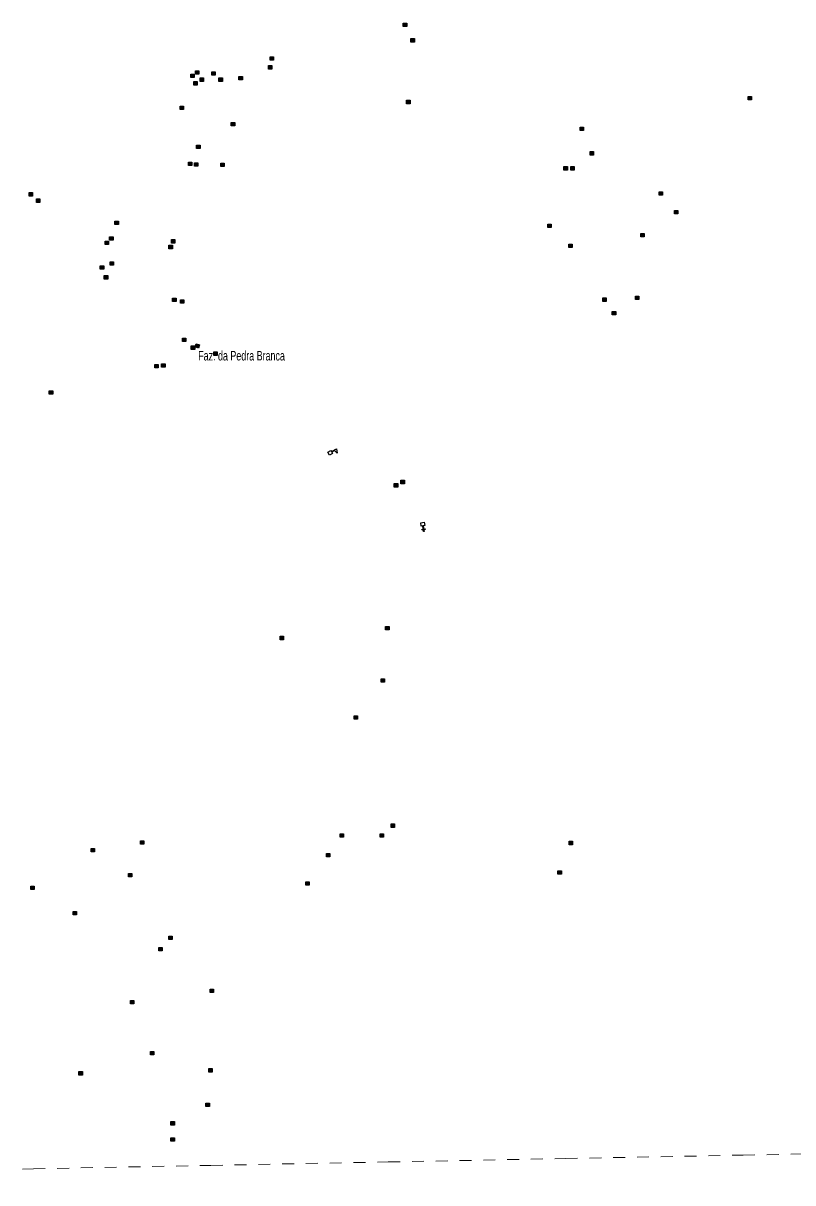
# Model space of a CAD drawing. Extents: x 220.8 to 246.7, y 7287.6 to 7315.8.
# Drawn here: x 227.18 to 233.65, y 7287.6 to 7297.35 of the extents above; entities that cross this region are included whole.
import ezdxf

# ---------------------------------------------------------------- set-up
doc = ezdxf.new("R2010")
doc.units = 0
doc.header["$LTSCALE"] = 0.032
doc.linetypes.add('SHORT_DASHED', pattern=[2.7, 1.5, -1.2])
for name, color, linetype, lineweight in [('2', 7, 'Continuous', 25), ('4', 7, 'Continuous', 25), ('58', 7, 'SHORT_DASHED', 13), ('6', 7, 'Continuous', 25)]:
    doc.layers.add(name, color=color, linetype=linetype, lineweight=lineweight)
doc.layers.add('61', color=7, linetype='Continuous')

msp = doc.modelspace()

# ---------------------------------------------------------------- hatches: boundary and pattern name
at = {"layer": '2'}
for points in [[(230.3759, 7297.3457), (230.4049, 7297.3457), (230.4049, 7297.3167), (230.3759, 7297.3167)], [(230.4409, 7297.2157), (230.4699, 7297.2157), (230.4699, 7297.1867), (230.4409, 7297.1867)], [(229.2429, 7296.9889), (229.2719, 7296.9889), (229.2719, 7296.9599), (229.2429, 7296.9599)], [(229.2571, 7297.063), (229.2861, 7297.063), (229.2861, 7297.034), (229.2571, 7297.034)], [(228.5899, 7296.9176), (228.6189, 7296.9176), (228.6189, 7296.8886), (228.5899, 7296.8886)], [(228.6298, 7296.9461), (228.6588, 7296.9461), (228.6588, 7296.9171), (228.6298, 7296.9171)], [(228.6697, 7296.8862), (228.6987, 7296.8862), (228.6987, 7296.8572), (228.6697, 7296.8572)], [(228.7667, 7296.9376), (228.7957, 7296.9376), (228.7957, 7296.9086), (228.7667, 7296.9086)], [(228.8266, 7296.8862), (228.8556, 7296.8862), (228.8556, 7296.8572), (228.8266, 7296.8572)], [(228.9948, 7296.8976), (229.0238, 7296.8976), (229.0238, 7296.8686), (228.9948, 7296.8686)], [(228.6156, 7296.8549), (228.6446, 7296.8549), (228.6446, 7296.8259), (228.6156, 7296.8259)], [(230.4039, 7296.6982), (230.4329, 7296.6982), (230.4329, 7296.6692), (230.4039, 7296.6692)], [(233.2744, 7296.7298), (233.3034, 7296.7298), (233.3034, 7296.7008), (233.2744, 7296.7008)], [(228.5015, 7296.6496), (228.5305, 7296.6496), (228.5305, 7296.6206), (228.5015, 7296.6206)], [(228.9304, 7296.5114), (228.9594, 7296.5114), (228.9594, 7296.4824), (228.9304, 7296.4824)], [(231.8628, 7296.4719), (231.8918, 7296.4719), (231.8918, 7296.4429), (231.8628, 7296.4429)], [(228.6396, 7296.322), (228.6686, 7296.322), (228.6686, 7296.293), (228.6396, 7296.293)], [(231.9459, 7296.2671), (231.9749, 7296.2671), (231.9749, 7296.2381), (231.9459, 7296.2381)], [(228.5702, 7296.178), (228.5992, 7296.178), (228.5992, 7296.149), (228.5702, 7296.149)], [(228.6209, 7296.1727), (228.6499, 7296.1727), (228.6499, 7296.1437), (228.6209, 7296.1437)], [(228.8424, 7296.17), (228.8714, 7296.17), (228.8714, 7296.141), (228.8424, 7296.141)], [(231.726, 7296.1413), (231.755, 7296.1413), (231.755, 7296.1123), (231.726, 7296.1123)], [(231.7833, 7296.1413), (231.8123, 7296.1413), (231.8123, 7296.1123), (231.7833, 7296.1123)], [(227.2319, 7295.9222), (227.2609, 7295.9222), (227.2609, 7295.8932), (227.2319, 7295.8932)], [(232.5251, 7295.9299), (232.5541, 7295.9299), (232.5541, 7295.9009), (232.5251, 7295.9009)], [(227.2935, 7295.8694), (227.3225, 7295.8694), (227.3225, 7295.8404), (227.2935, 7295.8404)], [(232.6541, 7295.7722), (232.6831, 7295.7722), (232.6831, 7295.7432), (232.6541, 7295.7432)], [(227.9532, 7295.6826), (227.9822, 7295.6826), (227.9822, 7295.6536), (227.9532, 7295.6536)], [(231.5898, 7295.6575), (231.6188, 7295.6575), (231.6188, 7295.6285), (231.5898, 7295.6285)], [(227.9085, 7295.5519), (227.9375, 7295.5519), (227.9375, 7295.5229), (227.9085, 7295.5229)], [(228.4278, 7295.5278), (228.4568, 7295.5278), (228.4568, 7295.4988), (228.4278, 7295.4988)], [(232.371, 7295.5787), (232.4, 7295.5787), (232.4, 7295.5497), (232.371, 7295.5497)], [(227.8707, 7295.5141), (227.8997, 7295.5141), (227.8997, 7295.4851), (227.8707, 7295.4851)], [(228.4071, 7295.4797), (228.4361, 7295.4797), (228.4361, 7295.4507), (228.4071, 7295.4507)], [(231.7662, 7295.4896), (231.7952, 7295.4896), (231.7952, 7295.4606), (231.7662, 7295.4606)], [(227.9119, 7295.3421), (227.9409, 7295.3421), (227.9409, 7295.3131), (227.9119, 7295.3131)], [(227.8294, 7295.3078), (227.8584, 7295.3078), (227.8584, 7295.2788), (227.8294, 7295.2788)], [(227.8638, 7295.2252), (227.8928, 7295.2252), (227.8928, 7295.1962), (227.8638, 7295.1962)], [(228.4381, 7295.0361), (228.4671, 7295.0361), (228.4671, 7295.0071), (228.4381, 7295.0071)], [(232.0521, 7295.0379), (232.0811, 7295.0379), (232.0811, 7295.0089), (232.0521, 7295.0089)], [(232.3265, 7295.0522), (232.3555, 7295.0522), (232.3555, 7295.0232), (232.3265, 7295.0232)], [(228.5034, 7295.0223), (228.5324, 7295.0223), (228.5324, 7294.9933), (228.5034, 7294.9933)], [(232.1321, 7294.9235), (232.1611, 7294.9235), (232.1611, 7294.8945), (232.1321, 7294.8945)], [(228.5198, 7294.6999), (228.5488, 7294.6999), (228.5488, 7294.6709), (228.5198, 7294.6709)], [(228.6359, 7294.6532), (228.6634, 7294.644), (228.6542, 7294.6165), (228.6267, 7294.6256)], [(228.595, 7294.6344), (228.624, 7294.6344), (228.624, 7294.6054), (228.595, 7294.6054)], [(228.7842, 7294.5835), (228.8132, 7294.5835), (228.8132, 7294.5545), (228.7842, 7294.5545)], [(228.287, 7294.4792), (228.316, 7294.4792), (228.316, 7294.4502), (228.287, 7294.4502)], [(228.3452, 7294.4841), (228.3742, 7294.4841), (228.3742, 7294.4551), (228.3452, 7294.4551)], [(227.4017, 7294.257), (227.4307, 7294.257), (227.4307, 7294.228), (227.4017, 7294.228)], [(230.3001, 7293.4774), (230.3291, 7293.4774), (230.3291, 7293.4484), (230.3001, 7293.4484)], [(230.3569, 7293.5058), (230.3859, 7293.5058), (230.3859, 7293.4768), (230.3569, 7293.4768)], [(230.2279, 7292.2771), (230.2569, 7292.2771), (230.2569, 7292.2481), (230.2279, 7292.2481)], [(229.3417, 7292.1953), (229.3707, 7292.1953), (229.3707, 7292.1663), (229.3417, 7292.1663)], [(230.1903, 7291.8385), (230.2193, 7291.8385), (230.2193, 7291.8095), (230.1903, 7291.8095)], [(229.9636, 7291.5279), (229.9926, 7291.5279), (229.9926, 7291.4989), (229.9636, 7291.4989)], [(230.2736, 7290.6188), (230.3026, 7290.6188), (230.3026, 7290.5898), (230.2736, 7290.5898)], [(228.1679, 7290.4762), (228.1969, 7290.4762), (228.1969, 7290.4472), (228.1679, 7290.4472)], [(229.8454, 7290.535), (229.8744, 7290.535), (229.8744, 7290.506), (229.8454, 7290.506)], [(230.1805, 7290.535), (230.2095, 7290.535), (230.2095, 7290.506), (230.1805, 7290.506)], [(231.7699, 7290.4726), (231.7989, 7290.4726), (231.7989, 7290.4436), (231.7699, 7290.4436)], [(227.7523, 7290.4124), (227.7813, 7290.4124), (227.7813, 7290.3834), (227.7523, 7290.3834)], [(229.7306, 7290.3706), (229.7596, 7290.3706), (229.7596, 7290.3416), (229.7306, 7290.3416)], [(228.0674, 7290.2026), (228.0964, 7290.2026), (228.0964, 7290.1736), (228.0674, 7290.1736)], [(231.6762, 7290.2249), (231.7052, 7290.2249), (231.7052, 7290.1959), (231.6762, 7290.1959)], [(227.2465, 7290.0961), (227.2755, 7290.0961), (227.2755, 7290.0671), (227.2465, 7290.0671)], [(229.5573, 7290.1332), (229.5863, 7290.1332), (229.5863, 7290.1042), (229.5573, 7290.1042)], [(227.6008, 7289.8829), (227.6298, 7289.8829), (227.6298, 7289.8539), (227.6008, 7289.8539)], [(228.3219, 7289.5803), (228.3509, 7289.5803), (228.3509, 7289.5513), (228.3219, 7289.5513)], [(228.4056, 7289.6759), (228.4346, 7289.6759), (228.4346, 7289.6469), (228.4056, 7289.6469)], [(228.7524, 7289.2306), (228.7814, 7289.2306), (228.7814, 7289.2016), (228.7524, 7289.2016)], [(228.0827, 7289.1361), (228.1117, 7289.1361), (228.1117, 7289.1071), (228.0827, 7289.1071)], [(228.2515, 7288.7066), (228.2805, 7288.7066), (228.2805, 7288.6776), (228.2515, 7288.6776)], [(227.6511, 7288.5381), (227.6801, 7288.5381), (227.6801, 7288.5091), (227.6511, 7288.5091)], [(228.7419, 7288.5626), (228.7709, 7288.5626), (228.7709, 7288.5336), (228.7419, 7288.5336)], [(228.718, 7288.2723), (228.747, 7288.2723), (228.747, 7288.2433), (228.718, 7288.2433)], [(228.4237, 7288.1172), (228.4527, 7288.1172), (228.4527, 7288.0882), (228.4237, 7288.0882)], [(228.4237, 7287.982), (228.4527, 7287.982), (228.4527, 7287.953), (228.4237, 7287.953)]]:
    msp.add_hatch(color=256, dxfattribs=at).paths.add_polyline_path(points)

# ---------------------------------------------------------------- linework, layer by layer
for points in [[(230.3759, 7297.3457), (230.4049, 7297.3457), (230.4049, 7297.3167), (230.3759, 7297.3167)], [(230.4409, 7297.2157), (230.4699, 7297.2157), (230.4699, 7297.1867), (230.4409, 7297.1867)], [(229.2429, 7296.9889), (229.2719, 7296.9889), (229.2719, 7296.9599), (229.2429, 7296.9599)], [(229.2571, 7297.063), (229.2861, 7297.063), (229.2861, 7297.034), (229.2571, 7297.034)], [(228.5899, 7296.9176), (228.6189, 7296.9176), (228.6189, 7296.8886), (228.5899, 7296.8886)], [(228.6298, 7296.9461), (228.6588, 7296.9461), (228.6588, 7296.9171), (228.6298, 7296.9171)], [(228.6697, 7296.8862), (228.6987, 7296.8862), (228.6987, 7296.8572), (228.6697, 7296.8572)], [(228.7667, 7296.9376), (228.7957, 7296.9376), (228.7957, 7296.9086), (228.7667, 7296.9086)], [(228.8266, 7296.8862), (228.8556, 7296.8862), (228.8556, 7296.8572), (228.8266, 7296.8572)], [(228.9948, 7296.8976), (229.0238, 7296.8976), (229.0238, 7296.8686), (228.9948, 7296.8686)], [(228.6156, 7296.8549), (228.6446, 7296.8549), (228.6446, 7296.8259), (228.6156, 7296.8259)], [(230.4039, 7296.6982), (230.4329, 7296.6982), (230.4329, 7296.6692), (230.4039, 7296.6692)], [(233.2744, 7296.7298), (233.3034, 7296.7298), (233.3034, 7296.7008), (233.2744, 7296.7008)], [(228.5015, 7296.6496), (228.5305, 7296.6496), (228.5305, 7296.6206), (228.5015, 7296.6206)], [(228.9304, 7296.5114), (228.9594, 7296.5114), (228.9594, 7296.4824), (228.9304, 7296.4824)], [(231.8628, 7296.4719), (231.8918, 7296.4719), (231.8918, 7296.4429), (231.8628, 7296.4429)], [(228.6396, 7296.322), (228.6686, 7296.322), (228.6686, 7296.293), (228.6396, 7296.293)], [(231.9459, 7296.2671), (231.9749, 7296.2671), (231.9749, 7296.2381), (231.9459, 7296.2381)], [(228.5702, 7296.178), (228.5992, 7296.178), (228.5992, 7296.149), (228.5702, 7296.149)], [(228.6209, 7296.1727), (228.6499, 7296.1727), (228.6499, 7296.1437), (228.6209, 7296.1437)], [(228.8424, 7296.17), (228.8714, 7296.17), (228.8714, 7296.141), (228.8424, 7296.141)], [(231.726, 7296.1413), (231.755, 7296.1413), (231.755, 7296.1123), (231.726, 7296.1123)], [(231.7833, 7296.1413), (231.8123, 7296.1413), (231.8123, 7296.1123), (231.7833, 7296.1123)], [(227.2319, 7295.9222), (227.2609, 7295.9222), (227.2609, 7295.8932), (227.2319, 7295.8932)], [(232.5251, 7295.9299), (232.5541, 7295.9299), (232.5541, 7295.9009), (232.5251, 7295.9009)], [(227.2935, 7295.8694), (227.3225, 7295.8694), (227.3225, 7295.8404), (227.2935, 7295.8404)], [(232.6541, 7295.7722), (232.6831, 7295.7722), (232.6831, 7295.7432), (232.6541, 7295.7432)], [(227.9532, 7295.6826), (227.9822, 7295.6826), (227.9822, 7295.6536), (227.9532, 7295.6536)], [(231.5898, 7295.6575), (231.6188, 7295.6575), (231.6188, 7295.6285), (231.5898, 7295.6285)], [(227.9085, 7295.5519), (227.9375, 7295.5519), (227.9375, 7295.5229), (227.9085, 7295.5229)], [(228.4278, 7295.5278), (228.4568, 7295.5278), (228.4568, 7295.4988), (228.4278, 7295.4988)], [(232.371, 7295.5787), (232.4, 7295.5787), (232.4, 7295.5497), (232.371, 7295.5497)], [(227.8707, 7295.5141), (227.8997, 7295.5141), (227.8997, 7295.4851), (227.8707, 7295.4851)], [(228.4071, 7295.4797), (228.4361, 7295.4797), (228.4361, 7295.4507), (228.4071, 7295.4507)], [(231.7662, 7295.4896), (231.7952, 7295.4896), (231.7952, 7295.4606), (231.7662, 7295.4606)], [(227.9119, 7295.3421), (227.9409, 7295.3421), (227.9409, 7295.3131), (227.9119, 7295.3131)], [(227.8294, 7295.3078), (227.8584, 7295.3078), (227.8584, 7295.2788), (227.8294, 7295.2788)], [(227.8638, 7295.2252), (227.8928, 7295.2252), (227.8928, 7295.1962), (227.8638, 7295.1962)], [(228.4381, 7295.0361), (228.4671, 7295.0361), (228.4671, 7295.0071), (228.4381, 7295.0071)], [(232.0521, 7295.0379), (232.0811, 7295.0379), (232.0811, 7295.0089), (232.0521, 7295.0089)], [(232.3265, 7295.0522), (232.3555, 7295.0522), (232.3555, 7295.0232), (232.3265, 7295.0232)], [(228.5034, 7295.0223), (228.5324, 7295.0223), (228.5324, 7294.9933), (228.5034, 7294.9933)], [(232.1321, 7294.9235), (232.1611, 7294.9235), (232.1611, 7294.8945), (232.1321, 7294.8945)], [(228.5198, 7294.6999), (228.5488, 7294.6999), (228.5488, 7294.6709), (228.5198, 7294.6709)], [(228.6359, 7294.6532), (228.6634, 7294.644), (228.6542, 7294.6165), (228.6267, 7294.6256)], [(228.595, 7294.6344), (228.624, 7294.6344), (228.624, 7294.6054), (228.595, 7294.6054)], [(228.7842, 7294.5835), (228.8132, 7294.5835), (228.8132, 7294.5545), (228.7842, 7294.5545)], [(228.287, 7294.4792), (228.316, 7294.4792), (228.316, 7294.4502), (228.287, 7294.4502)], [(228.3452, 7294.4841), (228.3742, 7294.4841), (228.3742, 7294.4551), (228.3452, 7294.4551)], [(227.4017, 7294.257), (227.4307, 7294.257), (227.4307, 7294.228), (227.4017, 7294.228)], [(230.3001, 7293.4774), (230.3291, 7293.4774), (230.3291, 7293.4484), (230.3001, 7293.4484)], [(230.3569, 7293.5058), (230.3859, 7293.5058), (230.3859, 7293.4768), (230.3569, 7293.4768)], [(230.2279, 7292.2771), (230.2569, 7292.2771), (230.2569, 7292.2481), (230.2279, 7292.2481)], [(229.3417, 7292.1953), (229.3707, 7292.1953), (229.3707, 7292.1663), (229.3417, 7292.1663)], [(230.1903, 7291.8385), (230.2193, 7291.8385), (230.2193, 7291.8095), (230.1903, 7291.8095)], [(229.9636, 7291.5279), (229.9926, 7291.5279), (229.9926, 7291.4989), (229.9636, 7291.4989)], [(230.2736, 7290.6188), (230.3026, 7290.6188), (230.3026, 7290.5898), (230.2736, 7290.5898)], [(228.1679, 7290.4762), (228.1969, 7290.4762), (228.1969, 7290.4472), (228.1679, 7290.4472)], [(229.8454, 7290.535), (229.8744, 7290.535), (229.8744, 7290.506), (229.8454, 7290.506)], [(230.1805, 7290.535), (230.2095, 7290.535), (230.2095, 7290.506), (230.1805, 7290.506)], [(231.7699, 7290.4726), (231.7989, 7290.4726), (231.7989, 7290.4436), (231.7699, 7290.4436)], [(227.7523, 7290.4124), (227.7813, 7290.4124), (227.7813, 7290.3834), (227.7523, 7290.3834)], [(229.7306, 7290.3706), (229.7596, 7290.3706), (229.7596, 7290.3416), (229.7306, 7290.3416)], [(228.0674, 7290.2026), (228.0964, 7290.2026), (228.0964, 7290.1736), (228.0674, 7290.1736)], [(231.6762, 7290.2249), (231.7052, 7290.2249), (231.7052, 7290.1959), (231.6762, 7290.1959)], [(227.2465, 7290.0961), (227.2755, 7290.0961), (227.2755, 7290.0671), (227.2465, 7290.0671)], [(229.5573, 7290.1332), (229.5863, 7290.1332), (229.5863, 7290.1042), (229.5573, 7290.1042)], [(227.6008, 7289.8829), (227.6298, 7289.8829), (227.6298, 7289.8539), (227.6008, 7289.8539)], [(228.3219, 7289.5803), (228.3509, 7289.5803), (228.3509, 7289.5513), (228.3219, 7289.5513)], [(228.4056, 7289.6759), (228.4346, 7289.6759), (228.4346, 7289.6469), (228.4056, 7289.6469)], [(228.7524, 7289.2306), (228.7814, 7289.2306), (228.7814, 7289.2016), (228.7524, 7289.2016)], [(228.0827, 7289.1361), (228.1117, 7289.1361), (228.1117, 7289.1071), (228.0827, 7289.1071)], [(228.2515, 7288.7066), (228.2805, 7288.7066), (228.2805, 7288.6776), (228.2515, 7288.6776)], [(227.6511, 7288.5381), (227.6801, 7288.5381), (227.6801, 7288.5091), (227.6511, 7288.5091)], [(228.7419, 7288.5626), (228.7709, 7288.5626), (228.7709, 7288.5336), (228.7419, 7288.5336)], [(228.718, 7288.2723), (228.747, 7288.2723), (228.747, 7288.2433), (228.718, 7288.2433)], [(228.4237, 7288.1172), (228.4527, 7288.1172), (228.4527, 7288.0882), (228.4237, 7288.0882)], [(228.4237, 7287.982), (228.4527, 7287.982), (228.4527, 7287.953), (228.4237, 7287.953)]]:
    msp.add_lwpolyline(points, close=True, dxfattribs=at)
at = {"layer": '4'}
for points in [[(229.7733, 7293.7462), (229.8157, 7293.7695), (229.8219, 7293.7342), (229.7986, 7293.7545), (229.7757, 7293.7419)], [(229.7757, 7293.7419), (229.7815, 7293.7313), (229.7561, 7293.7173), (229.7421, 7293.7427), (229.7676, 7293.7567), (229.7733, 7293.7462)]]:
    msp.add_lwpolyline(points, dxfattribs=at)
at = {"layer": '58'}
msp.add_lwpolyline([(221.3035, 7287.6034), (222.7945, 7287.633), (224.2855, 7287.6625), (225.7765, 7287.6918), (227.2675, 7287.7209), (228.7585, 7287.7499), (230.2495, 7287.7787), (231.7405, 7287.8074), (233.2315, 7287.836), (234.7225, 7287.8643), (236.2135, 7287.8925), (237.7045, 7287.9205), (239.1956, 7287.9483), (240.6866, 7287.9761), (242.1776, 7288.0036), (243.6686, 7288.031), (245.1597, 7288.0583), (246.6507, 7288.0853)], dxfattribs=at)
at = {"layer": '6'}
for points in [[(230.5393, 7293.1217), (230.5274, 7293.1198), (230.5227, 7293.1484), (230.5514, 7293.1531), (230.556, 7293.1245), (230.5441, 7293.1225)], [(230.5441, 7293.1225), (230.5484, 7293.0958), (230.5604, 7293.0977), (230.5612, 7293.0929), (230.5492, 7293.0909), (230.5518, 7293.0747), (230.5471, 7293.074), (230.5445, 7293.0902), (230.5325, 7293.0882), (230.5317, 7293.093), (230.5437, 7293.095), (230.5393, 7293.1217)]]:
    msp.add_lwpolyline(points, dxfattribs=at)

# ---------------------------------------------------------------- texts
at = {"layer": '61', "width": 0.7}
msp.add_text('Faz. da Pedra Branca', height=0.08, dxfattribs=at).set_placement((228.6527, 7294.5121))

doc.saveas('drawing.dxf')
